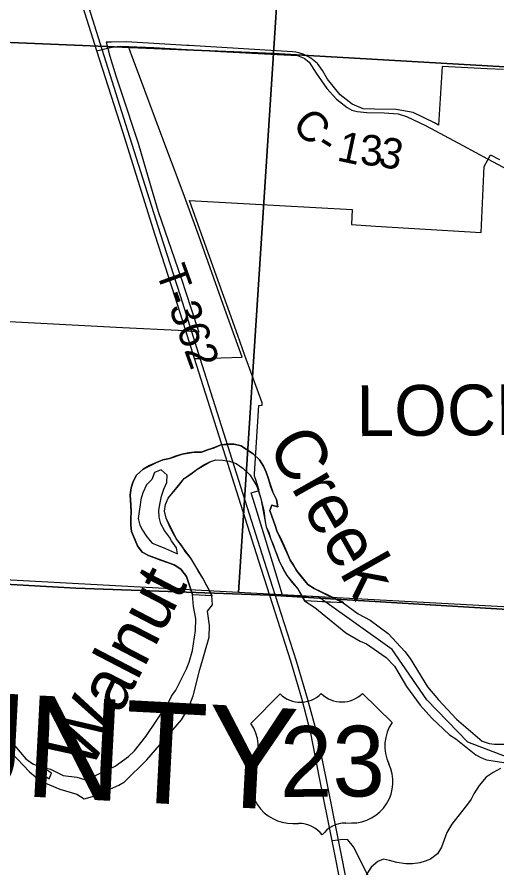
# Model space of a CAD drawing. Extents: x 114843 to 284848, y 317643 to 566895.
# Drawn here: x 205606 to 210335, y 326386 to 334768 of the extents above; entities that cross this region are included whole.
import ezdxf

# ---------------------------------------------------------------- set-up
doc = ezdxf.new("R2010")
doc.units = 0
for name, color, linetype in [('GM_X_Corporation', 7, 'Continuous'), ('GM_X_Corporation_Text', 7, 'Continuous'), ('GM_X_County', 7, 'Continuous'), ('GM_X_County_Road', 7, 'Continuous'), ('GM_X_County_Road_Text', 7, 'Continuous'), ('GM_X_County_Text', 7, 'Continuous'), ('GM_X_Major_River', 7, 'Continuous'), ('GM_X_Major_River_Text', 7, 'Continuous'), ('GM_X_Minor_River', 7, 'Continuous'), ('GM_X_Section', 7, 'Continuous'), ('GM_X_Township', 7, 'Continuous'), ('GM_X_Township_Road', 7, 'Continuous'), ('GM_X_Township_Road_Text', 7, 'Continuous'), ('GM_X_US_Location', 7, 'Continuous'), ('GM_X_US_Route', 7, 'Continuous'), ('GM_X_US_Shield', 7, 'Continuous')]:
    doc.layers.add(name, color=color, linetype=linetype)

msp = doc.modelspace()

# ---------------------------------------------------------------- linework, layer by layer
at = {"layer": 'GM_X_Corporation'}
for points in [[(210400.8, 334250.6), (210240.2, 334258.4), (209796.2, 334279.8), (209759.3, 333701.7), (209721.1, 333724.3), (209509.9, 333827.9), (209343.6, 333856.3), (209129.4, 333861.5), (209015.8, 333864.2), (208907.9, 333908.9), (208791.4, 334001.9), (208665.2, 334155.9), (208615.9, 334241.2), (208565.6, 334308.8), (208501.2, 334363.2), (208463.9, 334383.1), (208426.2, 334401.5), (208391.7, 334412.4), (208352, 334420.4), (208320.5, 334423.9), (207301.5, 334486.5), (207278, 334487.9), (206685.3, 334524.3), (206536, 334522.1), (206484.5, 334521.7), (206519.5, 334383.9), (206578.7, 334189.4), (206627.9, 334041.7), (206800, 333525.2), (206921.9, 333108.2), (206997.6, 332853.4), (207222.3, 332195.2), (207322.4, 331893.2), (207398.4, 331664.4), (207193.1, 331679.3), (206644.7, 331708.2), (204474.5, 331822.7)], [(210506, 327451), (210047.7, 327625.7), (209644.6, 328042.9), (209302.8, 328539.3), (208616.9, 329026.6), (208595.5, 329044.2), (208582.3, 329055.6), (208354.8, 329067.8), (208223.6, 329074.3), (208124.1, 329398.8), (207933.5, 330020), (207914.8, 330080.7), (207937.3, 330087.9), (207990.9, 330104.9), (207954.5, 330219.2), (207945.9, 330246.5), (207947.1, 330269.9), (207988.5, 330940.6), (208020.9, 330945.6), (208020.1, 330968.6), (207852.4, 331435.6), (207782.8, 331629.5), (207687.2, 331895.9), (207589.4, 332168.2), (207304.4, 332962.2), (208193.9, 332912.1), (208908.3, 332871.8), (208900.8, 332723.3), (209137.7, 332709.1), (210178.7, 332647), (210209.1, 333295), (210243.7, 333360.3), (210270, 333411.4), (210358.8, 333365.9)]]:
    msp.add_lwpolyline(points, dxfattribs=at)
at = {"layer": 'GM_X_County'}
for points in [[(234341.9, 327550.6), (226717.6, 328003.9), (223790.5, 328228.4), (218560.3, 328475.9), (218545.2, 328479.5), (213224.9, 328764.7), (208151.1, 329070.4), (208095.2, 329072.5), (206186.9, 329142.4), (202769.6, 329336.1), (202309.8, 329362.2), (198524.2, 329604), (197723.9, 329650.3), (193707.8, 329789.4), (193407.6, 329798.8), (192869.2, 329809.1), (189197.4, 329916.7), (185190.3, 330011.9), (181070.3, 330252.9), (177726, 330436.1)], [(177726, 330436.1), (181070.3, 330252.9), (185190.3, 330011.9), (189197.4, 329916.7), (192869.2, 329809.1), (193407.6, 329798.8), (193707.8, 329789.4), (197723.9, 329650.3), (198524.2, 329604), (202309.8, 329362.2), (202769.6, 329336.1), (206186.9, 329142.4), (208095.2, 329072.5), (208151.1, 329070.4), (213224.9, 328764.7), (218545.2, 328479.5), (218560.3, 328475.9), (223790.5, 328228.4), (226717.6, 328003.9), (234341.9, 327550.6)]]:
    msp.add_lwpolyline(points, dxfattribs=at)
at = {"layer": 'GM_X_County_Road'}
for points in [[(206394.1, 334435.4), (206446.3, 334448.3), (206496.9, 334462.2), (206561.2, 334475.1), (206622.2, 334480.2), (206705.3, 334476.8), (206955.3, 334466.5), (207612.7, 334428.9), (208171, 334399.7), (208371.3, 334389.6), (208435.4, 334363.5), (208483.5, 334323.4), (208553.6, 334215.1), (208659.6, 334062.8), (208753.8, 333958.5), (208857.9, 333878.2), (208903.9, 333852.2), (208958, 333838.1), (209052.2, 333828.1), (209224.5, 333824), (209362.7, 333815.9), (209442.8, 333789.8), (209631.1, 333699.5), (209997.6, 333503), (210240.6, 333372.4)], [(210240.6, 333372.4), (210740.7, 333103.8), (211047.1, 332921.3), (211141.2, 332821), (211205.3, 332762.8), (211387.5, 332646.5), (211645.9, 332500.1), (212467, 332010.6), (213407.4, 331506), (213503.8, 331430), (213705.7, 331312.4)]]:
    msp.add_lwpolyline(points, dxfattribs=at)
at = {"layer": 'GM_X_Major_River'}
for p, q in [((207334.4, 329079.6), (207527.5, 329069.2)), ((207334.4, 329079.6), (207531.1, 329069)), ((208437.8, 329020.3), (208823.2, 328999.7)), ((208512.5, 329016.3), (208716, 329005.4))]:
    msp.add_line(p, q, dxfattribs=at)
for points in [[(205580.3, 327593.2), (205694.4, 327462.8), (205761.2, 327411.7), (205823.6, 327386.7), (205935.9, 327360.5), (206060.9, 327298.4), (206194.8, 327279.6), (206270.7, 327257.2), (206330.5, 327273.5), (206573.6, 327388.6), (206704.9, 327485.3), (206762.6, 327541.6), (206873.8, 327680.4), (207091.9, 328003.8), (207129.5, 328078.1), (207171.2, 328138.4), (207276, 328349.3), (207303.7, 328413.5), (207335.1, 328529.9), (207366.1, 328726.4), (207369.6, 328838.7), (207345.1, 328960.9), (207336.1, 329079.5), (207275.6, 329258.4), (207221.2, 329330.2), (207155, 329373.8), (206902.8, 329464.4), (206840.6, 329498), (206792.3, 329557.8), (206733.5, 329699.7), (206727.2, 329761.7), (206732.4, 329897.9), (206721.4, 330062.1), (206731, 330132.2), (206750.6, 330194.5), (206782.2, 330254.7), (206847.7, 330313.2), (206979.2, 330380.1), (207043, 330406.6), (207108.8, 330419), (207234.4, 330461.8), (207352.1, 330480.6), (207424, 330483), (207615.4, 330554.3), (207747.2, 330561.1), (207815.2, 330543.5), (207933.5, 330466.2), (207993.8, 330406.5), (208036.2, 330342.6), (208062.5, 330284.7), (208127.6, 330086.8), (208162, 330014.9), (208176.4, 329944.9), (208118.3, 329958.6), (208098.7, 329906.4), (208119.1, 329840.4), (208169.9, 329698.5), (208297.4, 329418.9), (208359.9, 329317.2), (208470.6, 329179.7), (208534.8, 329138), (208820.6, 328999.5), (208966.8, 328888.6), (209084.9, 328826.9), (209263.2, 328695.3), (209427.8, 328519.5), (209480, 328449.5), (209649.1, 328171.5), (209757.5, 328041.7), (209936.1, 327851.9), (210188.7, 327634.3), (210256.7, 327612.5), (210310.6, 327604.7)], [(208823.2, 328999.7), (208534.8, 329138), (208470.6, 329179.7), (208410.2, 329253.4), (208359.9, 329317.2), (208331.6, 329369.1), (208297.4, 329418.9), (208264.9, 329496.8), (208234.6, 329564.7), (208202.2, 329636.6), (208169.9, 329698.5), (208145.4, 329770.5), (208119.1, 329840.4), (208098.7, 329906.4), (208118.3, 329958.6), (208176.4, 329944.9), (208162, 330014.9), (208127.6, 330086.8), (208105.2, 330150.8), (208084.8, 330218.7), (208062.5, 330284.7), (208036.2, 330342.6), (207993.8, 330406.5), (207933.5, 330466.2), (207867.4, 330507.8), (207815.2, 330543.5), (207747.2, 330561.1), (207683.3, 330560.8), (207615.4, 330554.3), (207547.7, 330523.9), (207481.9, 330503.4), (207424, 330483), (207352.1, 330480.6), (207300.2, 330474.3), (207234.4, 330461.8), (207168.6, 330441.4), (207108.8, 330419), (207043, 330406.6), (206979.2, 330380.1), (206911.5, 330349.7), (206847.7, 330313.2), (206782.2, 330254.7), (206750.6, 330194.5), (206731, 330132.2), (206721.4, 330062.1), (206723.7, 330012), (206728, 329962), (206732.4, 329897.9), (206728.8, 329825.8), (206727.2, 329761.7), (206733.5, 329699.7), (206763.9, 329631.7), (206792.3, 329557.8), (206840.6, 329498), (206902.8, 329464.4), (207022.9, 329417), (207155, 329373.8), (207221.2, 329330.2), (207275.6, 329258.4), (207334.4, 329079.6)], [(207334.4, 329079.6), (207275.6, 329258.4), (207221.2, 329330.2), (207155, 329373.8), (207022.9, 329417), (206902.8, 329464.4), (206840.6, 329498), (206792.3, 329557.8), (206763.9, 329631.7), (206733.5, 329699.7), (206727.2, 329761.7), (206728.8, 329825.8), (206732.4, 329897.9), (206728, 329962), (206723.7, 330012), (206721.4, 330062.1), (206731, 330132.2), (206750.6, 330194.5), (206782.2, 330254.7), (206847.7, 330313.2), (206911.5, 330349.7), (206979.2, 330380.1), (207043, 330406.6), (207108.8, 330419), (207168.6, 330441.4), (207234.4, 330461.8), (207300.2, 330474.3), (207352.1, 330480.6), (207424, 330483), (207481.9, 330503.4), (207547.7, 330523.9), (207615.4, 330554.3), (207683.3, 330560.8), (207747.2, 330561.1), (207815.2, 330543.5), (207867.4, 330507.8), (207933.5, 330466.2), (207993.8, 330406.5), (208036.2, 330342.6), (208062.5, 330284.7), (208084.8, 330218.7), (208105.2, 330150.8), (208127.6, 330086.8), (208162, 330014.9), (208176.4, 329944.9), (208118.3, 329958.6), (208098.7, 329906.4), (208119.1, 329840.4), (208145.4, 329770.5), (208169.9, 329698.5), (208202.2, 329636.6), (208234.6, 329564.7), (208264.9, 329496.8), (208297.4, 329418.9), (208331.6, 329369.1), (208359.9, 329317.2), (208410.2, 329253.4), (208470.6, 329179.7), (208534.8, 329138), (208822.4, 329000)], [(205547.5, 327522.5), (205728.5, 327333), (205803.5, 327270), (205864.1, 327231), (206029.2, 327161.5), (206196.4, 327114.8), (206267.6, 327066.8), (206373.3, 327095.3), (206608.4, 327200.4), (206666.2, 327234.6), (206886.8, 327449.9), (207228.4, 327844), (207293.8, 327954.5), (207341.2, 328080.9), (207405.9, 328341.7), (207498.2, 328660.8), (207501.7, 328773), (207483.1, 328917.3), (207530.7, 328977.6), (207526.7, 329069.3), (207437.5, 329241.4), (207318.4, 329436.9), (207173.4, 329630.3), (207074.4, 329831.9), (207058, 329899.9), (207067.5, 329968.1), (207095.1, 330030.4), (207253.8, 330221.6), (207377.1, 330312.5), (207506.5, 330387.4), (207566.3, 330405.8), (207634.3, 330402.2), (207698.2, 330394.6), (207766.3, 330369), (207832.5, 330323.3), (207898.8, 330257.7), (207941.1, 330195.8), (207969.4, 330145.9), (208010.1, 330026), (208061.7, 329745.9), (208191.6, 329402.3), (208266.3, 329268.5), (208371, 329139), (208438.7, 329018.7), (208541.2, 328953.2), (208845.9, 328701.8), (208986, 328620.1), (209050.1, 328594.3), (209244.4, 328458.7), (209324.6, 328374.8), (209443.4, 328172.8), (209578, 327988.9), (209694.4, 327861), (209868.9, 327697.3), (209929, 327659.4), (210127.4, 327499.8), (210181.5, 327470), (210233.5, 327452.1), (210425.3, 327422.8)], [(207527.5, 329069.2), (207469.8, 329177.5), (207437.5, 329241.4), (207393.1, 329305.2), (207356.8, 329371), (207318.4, 329436.9), (207266.1, 329500.7), (207225.8, 329564.5), (207173.4, 329630.3), (207135.1, 329702.1), (207106.7, 329764.1), (207074.4, 329831.9), (207058, 329899.9), (207067.5, 329968.1), (207095.1, 330030.4), (207148.7, 330092.8), (207200.3, 330155.2), (207253.8, 330221.6), (207317.5, 330266.1), (207377.1, 330312.5), (207440.8, 330353), (207506.5, 330387.4), (207566.3, 330405.8), (207634.3, 330402.2), (207698.2, 330394.6), (207766.3, 330369), (207832.5, 330323.3), (207898.8, 330257.7), (207941.1, 330195.8), (207969.4, 330145.9), (207991.8, 330080), (208010.1, 330026), (208026.5, 329958), (208036.8, 329906), (208045.1, 329850), (208051.4, 329795.9), (208061.7, 329745.9), (208086, 329690), (208108.4, 329624), (208128.6, 329574.1), (208146.9, 329524.1), (208169.2, 329468.2), (208191.6, 329402.3), (208228, 329330.4), (208266.3, 329268.5), (208318.7, 329198.8), (208371, 329139), (208437.8, 329020.3)], [(207527.4, 329069.4), (207469.8, 329177.5), (207437.5, 329241.4), (207393.1, 329305.2), (207356.8, 329371), (207318.4, 329436.9), (207266.1, 329500.7), (207225.8, 329564.5), (207173.4, 329630.3), (207135.1, 329702.1), (207106.7, 329764.1), (207074.4, 329831.9), (207058, 329899.9), (207067.5, 329968.1), (207095.1, 330030.4), (207148.7, 330092.8), (207200.3, 330155.2), (207253.8, 330221.6), (207317.5, 330266.1), (207377.1, 330312.5), (207440.8, 330353), (207506.5, 330387.4), (207566.3, 330405.8), (207634.3, 330402.2), (207698.2, 330394.6), (207766.3, 330369), (207832.5, 330323.3), (207898.8, 330257.7), (207941.1, 330195.8), (207969.4, 330145.9), (207991.8, 330080), (208010.1, 330026), (208026.5, 329958), (208036.8, 329906), (208045.1, 329850), (208051.4, 329795.9), (208061.7, 329745.9), (208086, 329690), (208108.4, 329624), (208128.6, 329574.1), (208146.9, 329524.1), (208169.2, 329468.2), (208191.6, 329402.3), (208228, 329330.4), (208266.3, 329268.5), (208318.7, 329198.8), (208371, 329139), (208438.7, 329018.7)], [(207025.6, 330306.3), (206959.8, 330281.9), (206934.2, 330213.6), (206880.6, 330159.2), (206847.1, 330080.9), (206827.6, 330014.7), (206817.9, 329964.5), (206808.3, 329896.4), (206800.7, 329828.2), (206817.1, 329764.3), (206841.3, 329714.3), (206883.7, 329646.5), (206938, 329586.8), (206998.1, 329561.1), (207068.1, 329533.5), (207128.2, 329505.8), (207188.3, 329480.2), (207176, 329540.2), (207127.6, 329610)], [(207127.6, 329610), (207109.4, 329643.9), (207059.1, 329711.7), (207022.8, 329775.6), (207006.4, 329841.5), (207002, 329911.6), (207015.5, 329981.8), (207031.1, 330050), (207052.7, 330118.2), (207082.2, 330184.5), (207085.8, 330256.6), (207025.6, 330306.3)], [(210310.6, 327604.7), (210456.4, 327605.3), (210600.1, 327619.8), (210737.7, 327660.4), (210869.1, 327733), (210936.8, 327785.4), (210984.5, 327841.7)], [(205875.8, 327367.5), (205860.9, 327307.1), (205899, 327280)], [(205899, 327280), (205921.5, 327264), (205944.6, 327318.6), (205875.8, 327367.5)]]:
    msp.add_lwpolyline(points, dxfattribs=at)
at = {"layer": 'GM_X_Minor_River'}
msp.add_lwpolyline([(210371.6, 327366.4), (210297.9, 327328.1), (210228.3, 327281.7), (210160.8, 327197.3), (210107.2, 327116.9), (210081.5, 327064.7), (210035.9, 327002.4), (209984.3, 326938.1), (209889, 326817.5), (209841.4, 326737.2), (209813.8, 326664.9), (209788.2, 326590.7), (209748.5, 326526.4), (209678.9, 326472), (209627.1, 326453.8), (209575.2, 326437.6), (209501.4, 326427.3), (209437.5, 326427), (209347.6, 326438.7), (209275.6, 326460.5), (209215.6, 326474.3), (209159.8, 326450.1), (209096.2, 326393.7), (209046.6, 326317.4)], dxfattribs=at)
at = {"layer": 'GM_X_Section'}
msp.add_lwpolyline([(208485.6, 339850.8), (208132.8, 334409.4), (202949.2, 334626.4), (203055.3, 336458.7)], dxfattribs=at)
for points in [[(208485.6, 339850.8), (213886.9, 339535.8), (213546, 334098.4), (208132.8, 334409.4)], [(202949.2, 334626.4), (208132.8, 334409.4), (207789.5, 329099.8), (202938, 329360.9), (202888.4, 329455.9), (202854.3, 329515.8), (202804.2, 329591.8), (202686, 329773.7)], [(208132.8, 334409.4), (213546, 334098.4), (213252.7, 328805.6), (207789.5, 329099.8)]]:
    msp.add_lwpolyline(points, close=True, dxfattribs=at)
at = {"layer": 'GM_X_Township'}
for points in [[(202908.7, 326135.9), (202904.2, 326408.6), (202925.2, 326713.8), (202965.1, 326836.8), (203088.7, 327107.6), (203133.3, 327311), (203173.2, 327434), (203239.3, 327551.4), (203415.1, 327801.1), (203516, 327989.3), (203544.2, 328098.1), (203544.3, 328212.4), (203498.6, 328442.3), (203481.7, 328494.2), (203419.9, 328609.5), (203250.3, 328829.3), (202992.1, 329093.7), (202862.3, 329211.9), (202769.6, 329336.1), (206186.9, 329142.4), (208095.2, 329072.5), (208151.1, 329070.4), (213224.9, 328764.7), (218545.2, 328479.5)], [(218545.2, 328479.5), (213224.9, 328764.7), (208151.1, 329070.4), (208095.2, 329072.5), (206186.9, 329142.4), (202769.6, 329336.1)]]:
    msp.add_lwpolyline(points, dxfattribs=at)
at = {"layer": 'GM_X_Township_Road'}
for points in [[(207355.6, 331404.2), (207410, 331406), (207823.6, 331419), (207653.4, 331891.5), (207379.6, 332658.3), (207243.1, 333036), (207024.6, 333621.9), (206813.4, 334185.5), (206737.5, 334385.1), (206705.3, 334476.8)], [(209555.2, 323536.5), (209530.8, 324244.2), (209527.8, 324688.8), (209519, 324991.1), (209494.6, 325161.3), (209472.3, 325287.4), (209391.7, 325563.6), (209181.3, 326082.9), (208921.7, 326595.2), (208864.5, 326663.1), (208811.2, 326666.2), (208774.1, 326661.3), (208711.6, 326652.8)]]:
    msp.add_lwpolyline(points, dxfattribs=at)
at = {"layer": 'GM_X_US_Route'}
for points in [[(207213.2, 331853.1), (207164.1, 332007.6), (206968.6, 332618.9), (206647.4, 333635.8), (206394.1, 334435.4), (206074.1, 335447.1), (205888.6, 336034.7), (205837, 336213.3), (205811.9, 336321.9), (205791.4, 336430.7), (205773.1, 336554.5), (205767.4, 336631.4)], [(206446.3, 334448.3), (206131.9, 335443.2), (205950.5, 336017.5), (205903.6, 336180.9), (205869.9, 336298.1), (205850.4, 336410.6), (205826.1, 336563.3), (205819.9, 336639)], [(207331.2, 331655.8), (207216.3, 332020.5), (207020.8, 332631.8), (206699.6, 333648.6), (206446.3, 334448.3)], [(208096.4, 329069.6), (207988.5, 329407.6), (207355.6, 331404.2), (207213.2, 331853.1)], [(208152.2, 329067.6), (208044.4, 329405.6), (207410, 331406), (207331.2, 331655.8)], [(209474.3, 320951.3), (209529.2, 321527.9), (209539.7, 321845.3), (209535.4, 322122.1), (209524.6, 322334), (209492.3, 322632.6), (209455.8, 322883.6), (209380, 323275.7), (209002.5, 325181.7), (208711.6, 326652.8), (208587.9, 327272.7), (208500.2, 327714.4), (208414.1, 328056.8), (208302.6, 328424.3), (208096.4, 329069.6)], [(209536.3, 320954.6), (209591.7, 321536.5), (209602.2, 321853.9), (209597.8, 322130.7), (209587.1, 322342.5), (209554.8, 322641.1), (209518.2, 322892.2), (209442.4, 323284.3), (209065, 325190.2), (208774.1, 326661.3), (208656.4, 327253.5), (208561.5, 327721.8), (208469.9, 328054.7), (208358.4, 328422.2), (208152.2, 329067.6)]]:
    msp.add_lwpolyline(points, dxfattribs=at)
at = {"layer": 'GM_X_US_Shield'}
for p, q in [((208197.4, 328100.5), (207909.5, 327808.4)), ((209301.7, 327818.4), (209009.6, 328106.4)), ((208322.7, 326825.1), (208380.7, 326825.5)), ((208844.8, 326828.9), (208902.8, 326829.3))]:
    msp.add_line(p, q, dxfattribs=at)
for centre, radius, start, end in [((208399, 328309.1), 290.1, 225.98632, 314.84032), ((208805.1, 328312), 290.1, 225.98632, 314.84033), ((207578.5, 327573), 406.1, 334.96044, 35.41424), ((209636.1, 327587.9), 406.1, 145.4124, 205.86621), ((208315.2, 327231.1), 406.1, 155.24523, 271.05157), ((208904.4, 327235.4), 406.1, 269.77507, 25.58141), ((208382.8, 326535.5), 290.1, 37.28322, 90.41332), ((208846.9, 326538.8), 290.1, 90.41332, 143.54342)]:
    msp.add_arc(centre, radius, start, end, dxfattribs=at)

# ---------------------------------------------------------------- texts
at = {"layer": 'GM_X_Corporation_Text'}
msp.add_text('LOCKBOURNE', height=500.04, rotation=0.41336, dxfattribs=at).set_placement((208952.3, 330639.1))
at = {"layer": 'GM_X_County_Road_Text'}
for s, rotation, p in [('C', 313.30717, (208304, 333696.8)), ('1', 347.97814, (208747.7, 333356.5)), ('3', 357.25404, (208981, 333311.2)), ('-', 328.0201, (208537.9, 333464.3)), ('3', 347.43104, (209152.2, 333304.2))]:
    msp.add_text(s, height=300, rotation=rotation, dxfattribs=at).set_placement(p)
at = {"layer": 'GM_X_County_Text'}
msp.add_text('PICKAWAY COUNTY', height=1000.08, rotation=356.99519, dxfattribs=at).set_placement((195279.2, 327637.7))
at = {"layer": 'GM_X_Major_River_Text'}
for s, height, rotation, p in [('Creek', 500.14, 299.51841, (208065.1, 330554.9)), ('Walnut', 500.12, 62.53237, (206328.1, 327331))]:
    msp.add_text(s, height=height, rotation=rotation, dxfattribs=at).set_placement(p)
at = {"layer": 'GM_X_Township_Road_Text'}
msp.add_text('T-362', height=300.02, rotation=289.82243, dxfattribs=at).set_placement((206970.9, 332264.3))
at = {"layer": 'GM_X_US_Location'}
for s, rotation, p in [('0', 0.41332, (208608, 327430.8)), ('/', 0.41332, (208608.1, 327430.8)), ('23', 0.41333, (208403.1, 327222.3))]:
    msp.add_text(s, height=1, rotation=rotation, dxfattribs=at).set_placement(p)
at = {"layer": 'GM_X_US_Shield'}
msp.add_text('23', height=696.15, rotation=0.41332, dxfattribs=at).set_placement((208197.5, 327085.3))

doc.saveas('drawing.dxf')
